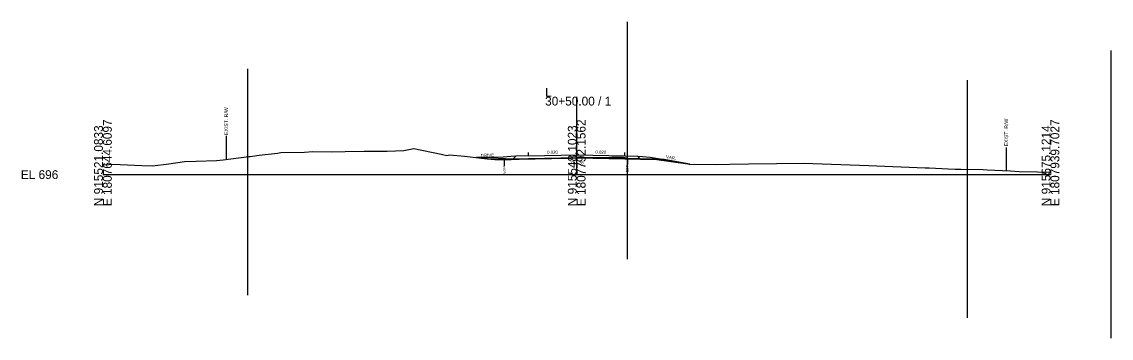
# Model space of a CAD drawing. Extents: x -26 to 1352, y -510 to 9596.
# Drawn here: x 974.3 to 1319.2, y 6448.2 to 6548.4 of the extents above; entities that cross this region are included whole.
import ezdxf

# ---------------------------------------------------------------- set-up
doc = ezdxf.new("R2010")
doc.units = 0
for name, color, linetype in [('Exist Cross Section Cell', 7, 'Continuous'), ('Exist XS Center Line Elevation Label', 7, 'Continuous'), ('Exist XS Ground Line', 7, 'Continuous'), ('Old_Level_10', 7, 'Continuous'), ('Prop XS Ditch Slope Text', 7, 'Continuous'), ('Prop XS Earthwork Shape', 7, 'Continuous'), ('Prop XS EOT Tick Mark', 7, 'Continuous'), ('Prop XS Exc Vertical Line 1', 7, 'Continuous'), ('Prop XS Exc Vertical Line 2', 7, 'Continuous'), ('Prop XS Exc Vertical Line 3', 7, 'Continuous'), ('Prop XS Exc Vertical Line 4', 7, 'Continuous'), ('Prop XS Finish Grade', 7, 'Continuous'), ('Prop XS Finish Grade Earthwork', 7, 'Continuous'), ('Prop XS Finish Grade Paved Shoulder', 7, 'Continuous'), ('Prop XS Finish Grade Pavement', 7, 'Continuous'), ('Prop XS Hydro Typical Ditch Data', 7, 'Continuous'), ('Prop XS Pvmt Edge Slope', 7, 'Continuous'), ('Prop XS SE Text', 7, 'Continuous'), ('Prop XS Subgrade Earthwork', 7, 'Continuous')]:
    doc.layers.add(name, color=color, linetype=linetype)

msp = doc.modelspace()

# ---------------------------------------------------------------- linework, layer by layer
at = {"layer": 'Exist Cross Section Cell'}
for p, q in [((1150, 6500), (1150, 6524.69)), ((1000, 6500), (1150, 6500)), ((1150, 6500), (1300, 6500))]:
    msp.add_line(p, q, dxfattribs=at)
at = {"layer": 'Exist XS Ground Line'}
msp.add_lwpolyline([(1000, 6503.06), (1003.7, 6503.26), (1005.48, 6503.24), (1012.29, 6502.86), (1015.65, 6502.74), (1020.89, 6503.41), (1025.81, 6504.15), (1029.48, 6504.22), (1035.98, 6504.49), (1038.07, 6504.73), (1046.15, 6505.77), (1046.66, 6505.78), (1049.5, 6506.17), (1055.26, 6506.83), (1056.31, 6506.99), (1063.85, 6507.08), (1066.48, 6507.3), (1072.44, 6507.18), (1076.64, 6507.3), (1082.73, 6507.48), (1084.15, 6507.47), (1090, 6507.38), (1095.23, 6507.65), (1098.47, 6508.23), (1107.04, 6506.47), (1108.93, 6506.08), (1109.68, 6506.25), (1114.46, 6505.83), (1121.7, 6504.98), (1124.08, 6504.79), (1125.06, 6504.81), (1126.36, 6504.78), (1127.02, 6504.75), (1128.85, 6504.83), (1129.04, 6504.84), (1129.07, 6504.84), (1129.28, 6504.84), (1131.77, 6504.91), (1132.85, 6504.95), (1134.31, 6505.01), (1135.32, 6505.02), (1136.86, 6505.04), (1137.48, 6505.06), (1139.39, 6505.1), (1140.09, 6505.12), (1140.88, 6505.13), (1141.93, 6505.16), (1142.07, 6505.16), (1143.77, 6505.19), (1144.48, 6505.19), (1145.11, 6505.2), (1145.35, 6505.2), (1145.59, 6505.21), (1147.02, 6505.24), (1148.14, 6505.26), (1149.19, 6505.28), (1149.24, 6505.28), (1149.57, 6505.28), (1150, 6505.28), (1150.37, 6505.28), (1152.1, 6505.27), (1152.51, 6505.28), (1154.64, 6505.33), (1154.78, 6505.33), (1157.18, 6505.33), (1158.95, 6505.36), (1159.72, 6505.37), (1160.25, 6505.37), (1161.09, 6505.38), (1161.53, 6505.38), (1162.27, 6505.38), (1163.96, 6505.38), (1164.81, 6505.38), (1165.75, 6505.25), (1166.04, 6505.21), (1167.95, 6505.16), (1169.29, 6505.13), (1170.12, 6505.1), (1174.31, 6504.99), (1185.2, 6503.42), (1185.75, 6503.36), (1185.81, 6503.36), (1193.79, 6503.25), (1198.53, 6503.29), (1204.35, 6503.37), (1222.07, 6503.62), (1224.74, 6503.51), (1242.49, 6502.85), (1260.36, 6502.15), (1261.61, 6502.11), (1267.58, 6501.83), (1269.8, 6501.73), (1270.08, 6501.72), (1271.57, 6501.7), (1278.67, 6501.61), (1279.97, 6501.56), (1287.26, 6501.18), (1290.14, 6501.03), (1295.85, 6500.84), (1300, 6500.74)], dxfattribs=at)
at = {"layer": 'Old_Level_10'}
for p, q in [((1039.03, 6512.25), (1039.03, 6504.85)), ((1286.01, 6508.64), (1286.01, 6501.24)), ((1127.02, 6504.75), (1127.02, 6502.7)), ((1166.04, 6505.21), (1166.04, 6503.16))]:
    msp.add_line(p, q, dxfattribs=at)
at = {"layer": 'Prop XS Earthwork Shape'}
for points in [[(1149.57, 6505.28), (1150, 6505.28), (1150.37, 6505.28), (1152.1, 6505.27), (1152.51, 6505.28), (1152.8, 6505.29), (1150, 6505.34), (1134.72, 6505.04), (1129.78, 6504.94), (1118.31, 6505.38), (1121.7, 6504.98), (1124.08, 6504.79), (1125.06, 6504.81), (1126.36, 6504.78), (1127.02, 6504.75), (1128.85, 6504.83), (1129.04, 6504.84), (1129.07, 6504.84), (1129.28, 6504.84), (1131.77, 6504.91), (1132.85, 6504.95), (1134.31, 6505.01), (1135.32, 6505.02), (1136.86, 6505.04), (1137.48, 6505.06), (1139.39, 6505.1), (1140.09, 6505.12), (1140.88, 6505.13), (1141.93, 6505.16), (1142.07, 6505.16), (1143.77, 6505.19), (1144.48, 6505.19), (1145.11, 6505.2), (1145.35, 6505.2), (1145.59, 6505.21), (1147.02, 6505.24), (1148.14, 6505.26), (1149.19, 6505.28), (1149.24, 6505.28)], [(1149.24, 6505.28), (1149.57, 6505.28), (1150, 6505.28), (1150.37, 6505.28), (1152.1, 6505.27), (1152.51, 6505.28), (1152.8, 6505.29), (1150, 6505.34), (1134.72, 6505.04), (1129.78, 6504.94), (1118.31, 6505.38), (1121.7, 6504.98), (1124.08, 6504.79), (1125.06, 6504.81), (1126.36, 6504.78), (1127.02, 6504.75), (1128.85, 6504.83), (1129.04, 6504.84), (1129.07, 6504.84), (1129.28, 6504.84), (1131.77, 6504.91), (1132.85, 6504.95), (1134.31, 6505.01), (1135.32, 6505.02), (1136.86, 6505.04), (1137.48, 6505.06), (1139.39, 6505.1), (1140.09, 6505.12), (1140.88, 6505.13), (1141.93, 6505.16), (1142.07, 6505.16), (1143.77, 6505.19), (1144.48, 6505.19), (1145.11, 6505.2), (1145.35, 6505.2), (1145.59, 6505.21), (1147.02, 6505.24), (1148.14, 6505.26), (1149.19, 6505.28)], [(1149.24, 6505.28), (1149.57, 6505.28), (1150, 6505.28), (1150.37, 6505.28), (1152.1, 6505.27), (1152.51, 6505.28), (1152.8, 6505.29), (1150, 6505.34), (1134.72, 6505.04), (1129.78, 6504.94), (1118.31, 6505.38), (1121.7, 6504.98), (1124.08, 6504.79), (1125.06, 6504.81), (1126.36, 6504.78), (1127.02, 6504.75), (1128.85, 6504.83), (1129.04, 6504.84), (1129.07, 6504.84), (1129.28, 6504.84), (1131.77, 6504.91), (1132.85, 6504.95), (1134.31, 6505.01), (1135.32, 6505.02), (1136.86, 6505.04), (1137.48, 6505.06), (1139.39, 6505.1), (1140.09, 6505.12), (1140.88, 6505.13), (1141.93, 6505.16), (1142.07, 6505.16), (1143.77, 6505.19), (1144.48, 6505.19), (1145.11, 6505.2), (1145.35, 6505.2), (1145.59, 6505.21), (1147.02, 6505.24), (1148.14, 6505.26), (1149.19, 6505.28)], [(1166.04, 6505.02), (1166.04, 6505.21), (1165.75, 6505.25), (1164.81, 6505.38), (1163.96, 6505.38), (1162.27, 6505.38), (1161.53, 6505.38), (1161.09, 6505.38), (1160.25, 6505.37), (1159.72, 6505.37), (1158.95, 6505.36), (1157.18, 6505.33), (1154.78, 6505.33), (1154.64, 6505.33), (1152.8, 6505.29), (1165.28, 6505.04)], [(1152.8, 6505.29), (1154.64, 6505.33), (1154.78, 6505.33), (1157.18, 6505.33), (1158.95, 6505.36), (1159.72, 6505.37), (1160.25, 6505.37), (1161.09, 6505.38), (1161.53, 6505.38), (1162.27, 6505.38), (1163.96, 6505.38), (1164.81, 6505.38), (1165.75, 6505.25), (1166.04, 6505.21), (1166.04, 6505.02), (1165.28, 6505.04)], [(1152.8, 6505.29), (1154.64, 6505.33), (1154.78, 6505.33), (1157.18, 6505.33), (1158.95, 6505.36), (1159.72, 6505.37), (1160.25, 6505.37), (1161.09, 6505.38), (1161.53, 6505.38), (1162.27, 6505.38), (1163.96, 6505.38), (1164.81, 6505.38), (1165.75, 6505.25), (1166.04, 6505.21), (1166.04, 6505.02), (1165.28, 6505.04)], [(1169.29, 6505.13), (1170.12, 6505.1), (1174.31, 6504.99), (1175.39, 6504.84), (1170.22, 6504.94), (1166.04, 6505.02), (1166.04, 6505.21), (1167.95, 6505.16)], [(1174.31, 6504.99), (1175.39, 6504.84), (1170.22, 6504.94), (1166.04, 6505.02), (1166.04, 6505.21), (1167.95, 6505.16), (1169.29, 6505.13), (1170.12, 6505.1)], [(1175.39, 6504.84), (1185.2, 6503.42), (1185.75, 6503.36), (1185.81, 6503.36), (1177.64, 6504.79)], [(1175.39, 6504.84), (1185.2, 6503.42), (1185.75, 6503.36), (1185.81, 6503.36), (1177.64, 6504.79)]]:
    msp.add_lwpolyline(points, close=True, dxfattribs=at)
at = {"layer": 'Prop XS EOT Tick Mark'}
for p, q in [((1134.72, 6505.96), (1134.72, 6506.96)), ((1165.28, 6505.96), (1165.28, 6506.96))]:
    msp.add_line(p, q, dxfattribs=at)
at = {"layer": 'Prop XS Exc Vertical Line 1'}
msp.add_line((1045.83, 6461.84), (1045.83, 6533.49), dxfattribs=at)
at = {"layer": 'Prop XS Exc Vertical Line 2'}
msp.add_line((1166.04, 6473.2), (1166.04, 6548.43), dxfattribs=at)
at = {"layer": 'Prop XS Exc Vertical Line 3'}
msp.add_line((1273.75, 6454.67), (1273.75, 6529.91), dxfattribs=at)
at = {"layer": 'Prop XS Exc Vertical Line 4'}
msp.add_line((1319.23, 6448.16), (1319.23, 6539.35), dxfattribs=at)
at = {"layer": 'Prop XS Finish Grade'}
for p, q in [((1126.72, 6505.56), (1118.31, 6505.38)), ((1129.14, 6505.75), (1126.72, 6505.56)), ((1130.72, 6505.88), (1129.14, 6505.75)), ((1169.28, 6505.88), (1170.86, 6505.75)), ((1170.86, 6505.75), (1173.28, 6505.56)), ((1173.28, 6505.56), (1177.64, 6504.79))]:
    msp.add_line(p, q, dxfattribs=at)
at = {"layer": 'Prop XS Finish Grade Earthwork'}
msp.add_line((1177.64, 6504.79), (1185.81, 6503.36), dxfattribs=at)
at = {"layer": 'Prop XS Finish Grade Paved Shoulder'}
for p, q in [((1134.72, 6505.96), (1130.72, 6505.88)), ((1165.28, 6505.96), (1169.28, 6505.88))]:
    msp.add_line(p, q, dxfattribs=at)
at = {"layer": 'Prop XS Finish Grade Pavement'}
for p, q in [((1134.72, 6505.96), (1150, 6506.26)), ((1150, 6506.26), (1165.28, 6505.96))]:
    msp.add_line(p, q, dxfattribs=at)
at = {"layer": 'Prop XS Hydro Typical Ditch Data'}
msp.add_line((1173.28, 6505.56), (1185.81, 6503.36), dxfattribs=at)
at = {"layer": 'Prop XS Pvmt Edge Slope'}
for p, q in [((1130.72, 6505.88), (1129.78, 6504.94)), ((1169.28, 6505.88), (1170.22, 6504.94))]:
    msp.add_line(p, q, dxfattribs=at)
at = {"layer": 'Prop XS Subgrade Earthwork'}
for p, q in [((1129.78, 6504.94), (1118.31, 6505.38)), ((1134.72, 6505.04), (1150, 6505.34)), ((1150, 6505.34), (1165.28, 6505.04)), ((1134.72, 6505.04), (1129.78, 6504.94)), ((1165.28, 6505.04), (1170.22, 6504.94)), ((1170.22, 6504.94), (1177.64, 6504.79))]:
    msp.add_line(p, q, dxfattribs=at)

# ---------------------------------------------------------------- texts
at = {"layer": 'Exist Cross Section Cell'}
for s, p in [('L', (1140, 6524.69)), ('30+50.00 / 1', (1140, 6521.89)), ('EL 696', (974, 6498.6))]:
    msp.add_text(s, height=2.8, dxfattribs=at).set_placement(p)
for s, p in [('E 1807644.6097', (1002.8, 6490)), ('E 1807792.1562', (1152.8, 6490)), ('E 1807939.7027', (1302.8, 6490)), ('N 915521.0833', (1000, 6490)), ('N 915548.1023', (1150, 6490)), ('N 915575.1214', (1300, 6490))]:
    msp.add_text(s, height=2.8, rotation=90, dxfattribs=at).set_placement(p)
at = {"layer": 'Exist XS Center Line Elevation Label'}
msp.add_text('701.28', height=1, dxfattribs=at).set_placement((1147.95, 6503.28))
at = {"layer": 'Old_Level_10'}
for s, height, p in [('EXIST. R/W', 1.181, (1039.62, 6512.55)), ('EXIST. R/W', 1.181, (1286.6, 6508.95)), ('EOP', 0.787, (1127.41, 6500.3)), ('EOP', 0.787, (1166.43, 6500.76))]:
    msp.add_text(s, height=height, rotation=90, dxfattribs=at).set_placement(p)
at = {"layer": 'Prop XS Ditch Slope Text'}
for s, rotation, p in [('DRIVE', 2.4925, (1119.66, 6505.55)), ('VAR.', 350.0573, (1178.21, 6505.19))]:
    msp.add_text(s, height=1, rotation=rotation, dxfattribs=at).set_placement(p)
at = {"layer": 'Prop XS SE Text'}
for rotation, p in [(1.1458, (1140.61, 6506.57)), (358.8542, (1155.89, 6506.64))]:
    msp.add_text('0.020', height=1, rotation=rotation, dxfattribs=at).set_placement(p)

doc.saveas('drawing.dxf')
